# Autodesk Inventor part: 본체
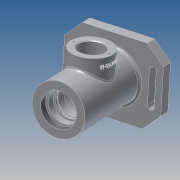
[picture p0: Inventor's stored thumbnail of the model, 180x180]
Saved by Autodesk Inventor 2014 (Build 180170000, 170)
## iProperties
Created: 2017-10
Part Number: 본체
Material: 알루미늄 6061
Document SubType Name: Modeling
Designer: kb543-05
Mass: 790.067 g
Surface Area: 665.368 cm^2
Volume: 291.538 cm^3
Density: 2.71 g/cm^3
Appearance: 알루미늄 - 평지
Author: kb543-05
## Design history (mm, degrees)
sketch "스케치2"
  geometry: L1 (0, 0)-(31, 0); L2 (31, 0)-(31, -99); L3 (31, -99)-(0, -99); L4 (0, -99)-(0, 0)
  constraints: 8 end point, 2 parallel, 1 horizontal, 1 perpendicular
  dimensions: "d1" = 99 distance of L1.end L2.end; "d2" = 62 diameter of L2 L4
revolve "회전1" sketch "스케치2" stored, may be unused: angle "d3" = 90 deg
sketch "스케치3"
  geometry: L1 (-58, 47)-(58, 47); L2 (58, 47)-(58, -47); L3 (58, -47)-(-58, -47); L4 (-58, -47)-(-58, 47); L5 (-87.549, 0)-(134.549, 0); L6 (0, 69.118)-(0, -96.765); L7 (-46, 20)-(-46, -20); L8 (-50, 20)-(-50, -20); L9 (-42, -20)-(-42, 20); L10 (46, 18)-(46, -22); L11 (42, 18)-(42, -22); L12 (50, -22)-(50, 18); C1 r 31 at (0, 0) reference; C2 r 31 at (0, 0); A1 r 4 centre (-46, 20) between (-42, 20) and (-50, 20); A2 r 4 centre (-46, -20) between (-50, -20) and (-42, -20); A3 r 4 centre (46, 18) between (50, 18) and (42, 18); A4 r 4 centre (46, -22) between (42, -22) and (50, -22); 5 further points
  constraints: 28 end point, 8 point on circle, 8 tangent, 7 parallel, 5 centre point, 5 midpoint, 3 perpendicular, 2 equal radius, 2 horizontal alignment, 2 point on line, 1 coincident, 1 horizontal, 1 vertical alignment
  dimensions: "d4" = 94 distance of L1.end L2.end; "d5" = 116 distance of L1.start L1.end; "d6" = 40 distance of L7.start L7.end; "d7" = 46 distance between parallel lines of L7 L6; "d8" = 4 radius of A1; "d9" = 92 distance between parallel lines of L7 L10
extrude "돌출1" join sketch "스케치3" distance "d10" = 13; taper "d11" = 0 deg
chamfer "모따기1" distance "d12" = 20; stored, may be unused: second distance "d13" = 2, angle "d14" = 45 deg
sketch "스케치4"
  geometry: C1 r 35 at (0, 0); 1 further point
  constraints: 1 centre point, 1 coincident
  dimensions: "d15" = 70 diameter of C1
extrude "돌출2" join sketch "스케치4" distance "d16" = 3; taper "d17" = 0 deg
sketch "스케치5"
  geometry: L1 (-31, -99)-(31, -99) reference; L2 (-31, 0)-(31, 0) reference; L3 (47, -112)-(27, -112) reference; L4 (27, -112)-(27, -99) reference; L5 (27, -99)-(47, -99) reference; L6 (47, -99)-(47, -112) reference; L7 (-35, -115)-(35, -115) reference; L8 (35, -112)-(-35, -112) reference; L9 (18, -99)-(-22, -99) reference; L10 (18, -99)-(18, -112) reference; L11 (-22, -112)-(18, -112) reference; L12 (-22, -99)-(-22, -112) reference; L13 (-35, -112)-(-47, -112) reference; L14 (-47, -112)-(-47, -99) reference; L15 (-47, -99)-(-31, -99) reference; L16 (-31, -99)-(-31, 0) reference; L17 (-31, 0)-(31, 0) reference; L18 (31, 0)-(31, -99) reference; L19 (0, 0)-(21, 0); L20 (21, 0)-(21, -9); L21 (21, -9)-(0, -9); L22 (0, -9)-(0, 0); L23 (0, -9)-(24, -9); L24 (24, -9)-(24, -12); L25 (24, -12)-(0, -12); L26 (0, -12)-(0, -9); L27 (0, -12)-(20, -12); L28 (20, -12)-(20, -21); L29 (20, -21)-(0, -21); L30 (0, -21)-(0, -12); L31 (0, -21)-(17.5, -21); L32 (17.5, -21)-(17.5, -37); L33 (17.5, -37)-(0, -37); L34 (0, -37)-(0, -21); L35 (0, -24.25)-(18.5, -24.25); L36 (18.5, -24.25)-(18.5, -26); L37 (18.5, -26)-(0, -26); L38 (0, -26)-(0, -24.25); L39 (0, -37)-(26, -37); L40 (26, -37)-(26, -75); L41 (26, -75)-(0, -75); L42 (0, -75)-(0, -37); L43 (0, -75)-(17.5, -75); L44 (17.5, -75)-(17.5, -86); L45 (17.5, -86)-(0, -86); L46 (0, -86)-(0, -75); L47 (0, -86)-(16.5, -86); L48 (16.5, -86)-(16.5, -91); L49 (16.5, -91)-(0, -91); L50 (0, -91)-(0, -86); L51 (0, -91)-(10, -91); L52 (10, -91)-(10, -93.7); L53 (10, -93.7)-(0, -93.7); L54 (0, -93.7)-(0, -91); L55 (0, -93.7)-(12.5, -93.7); L56 (12.5, -93.7)-(12.5, -101); L57 (12.5, -101)-(0, -101); L58 (0, -101)-(0, -93.7); L59 (0, -115)-(22, -115); L60 (22, -115)-(16, -101); L61 (16, -101)-(0, -101); L62 (0, -101)-(0, -115); L63 (31, -99)-(47, -99) reference; L64 (47, -99)-(47, -112) reference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
  constraints: 92 end point, 21 parallel, 13 perpendicular, 10 horizontal, 4 point on line, 2 collinear
  dimensions: "d19" = 12 distance between parallel lines of L25 L2; "d20" = 3 distance of L23.end L24.end; "d21" = 21 distance between parallel lines of L19 L29; "d22" = 26 distance between parallel lines of L37 L2; "d23" = 38 distance between parallel lines of L41 L39; "d24" = 60 distance between parallel lines of L45 L37; "d25" = 11 distance between parallel lines of L33 L37; "d26" = 1.75 distance between parallel lines of L37 L35; "d27" = 5 distance between parallel lines of L49 L45; "d29" = 7.3 distance of L55.end L56.end; "d30" = 44 diameter of L59.end L62; "d31" = 32 diameter of L60.end L62; "d32" = 25 diameter of L56 L58; "d34" = 14 distance of L61.end L59.start; "d35" = 2.7 distance between parallel lines of L53 L49; "d36" = 42 diameter of L20 L22; "d37" = 48 diameter of L24 L26; "d38" = 40 diameter of L28 L30; "d39" = 35 diameter of L32 L34; "d40" = 37 diameter of L36 L38; "d41" = 52 diameter of L40 L42; "d42" = 35 diameter of L44 L46; "d43" = 33 diameter of L48 L50; "d44" = 20 diameter of L52 L54; "d45" = 11 distance between parallel lines of L41 L45 (derived); "d46" = 30 deg angle of L56 L69; "d47" = 0.7 distance between parallel lines of L68 L61
revolve "회전2" sketch "스케치5" stored, may be unused: angle "d48" = 90 deg
feature "스레드1" dims "d49" = 10, "d50" = 0
sketch "스케치6"
  geometry: L1 (-58, -99)-(-50, -99) reference; L2 (-50, -99)-(-50, -112) reference; L3 (-50, -112)-(-58, -112) reference; L4 (-58, -112)-(-58, -99) reference; L5 (-42, -99)-(-31, -99) reference; L6 (-31, -99)-(-31, 0) reference; L7 (-31, 0)-(-21, 0) reference; L8 (-21, 0)-(-21, -9) reference; L9 (-21, -9)-(-24, -9) reference; L10 (-24, -9)-(-24, -12) reference; L11 (-24, -12)-(-20, -12) reference; L12 (-20, -12)-(-20, -21) reference; L13 (-20, -21)-(-17.5, -21) reference; L14 (-17.5, -21)-(-17.5, -24.25) reference; L15 (-17.5, -24.25)-(-18.5, -24.25) reference; L16 (-18.5, -24.25)-(-18.5, -26) reference; L17 (-18.5, -26)-(-17.5, -26) reference; L18 (-17.5, -26)-(-17.5, -37) reference; L19 (-17.5, -37)-(-26, -37) reference; L20 (-26, -37)-(-26, -75) reference; L21 (-26, -75)-(-17.5, -75) reference; L22 (-17.5, -75)-(-17.5, -86) reference; L23 (-17.5, -86)-(-16.5, -86) reference; L24 (-16.5, -86)-(-16.5, -91) reference; L25 (-16.5, -91)-(-10, -91) reference; L26 (-10, -91)-(-10, -93.7) reference; L27 (-10, -93.7)-(-12.5, -93.7) reference; L28 (-12.5, -93.7)-(-12.5, -101) reference; L29 (-12.5, -101)-(-16, -101) reference; L30 (-16, -101)-(-22, -115) reference; L31 (-22, -115)-(-35, -115) reference; L32 (-35, -115)-(-35, -112) reference; L33 (-35, -112)-(-42, -112) reference; L34 (-42, -112)-(-42, -99) reference; L35 (31, -99)-(42, -99) reference; L36 (42, -99)-(42, -112) reference; L37 (42, -112)-(35, -112) reference; L38 (35, -112)-(35, -115) reference; L39 (35, -115)-(22, -115) reference; L40 (22, -115)-(16, -101) reference; L41 (16, -101)-(12.5, -101) reference; L42 (12.5, -101)-(12.5, -93.7) reference; L43 (12.5, -93.7)-(10, -93.7) reference; L44 (10, -93.7)-(10, -91) reference; L45 (10, -91)-(16.5, -91) reference; L46 (16.5, -91)-(16.5, -86) reference; L47 (16.5, -86)-(17.5, -86) reference; L48 (17.5, -86)-(17.5, -75) reference; L49 (17.5, -75)-(26, -75) reference; L50 (26, -75)-(26, -37) reference; L51 (26, -37)-(17.5, -37) reference; L52 (17.5, -37)-(17.5, -26) reference; L53 (17.5, -26)-(18.5, -26) reference; L54 (18.5, -26)-(18.5, -24.25) reference; L55 (18.5, -24.25)-(17.5, -24.25) reference; L56 (17.5, -24.25)-(17.5, -21) reference; L57 (17.5, -21)-(20, -21) reference; L58 (20, -21)-(20, -12) reference; L59 (20, -12)-(24, -12) reference; L60 (24, -12)-(24, -9) reference; L61 (24, -9)-(21, -9) reference; L62 (21, -9)-(21, 0) reference; L63 (21, 0)-(31, 0) reference; L64 (31, 0)-(31, -99) reference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; C1 r 25 at (0, -56)
  constraints: 4 end point, 3 midpoint, 1 centre point, 1 perpendicular, 1 point on line
  dimensions: "d52" = 50 diameter of C1
  node "절단 모서리 투영2"
node "작업 평면1"
sketch "스케치7"
  geometry: L1 (0, 0)-(0, -139); L2 (-69, -56)-(82, -56); L3 (-31, 0)-(31, 0) reference; C1 r 25 at (0, -56)
  constraints: 4 end point, 2 point on line, 1 centre point, 1 perpendicular, 1 vertical
  dimensions: "d54" = 56 distance between parallel lines of L2 L3; "d55" = 50 diameter of C1
extrude "돌출3" join sketch "스케치7" stored distance "d56" = 3; taper "d57" = 0 deg
sketch "스케치8"
  geometry: C1 r 25 at (0, 0) reference; C2 r 16 at (0, 0); 1 further point
  constraints: 1 centre point, 1 coincident
  dimensions: "d58" = 32 diameter of C2
extrude "돌출4" cut sketch "스케치8" stored distance "d59" = 3; taper "d60" = 0 deg
sketch "스케치9"
  geometry: C1 r 25 at (0, 0) reference; A1 r 20.5 centre (0, 0) between (20.5, 0) and (-20.5, 0); 1 further point
  constraints: 2 point on circle, 1 centre point, 1 coincident
  dimensions: "d61" = 41 diameter of A1
hole "구멍1" sketch "스케치9" at (20.5, 0), (-20.5, 0) diameter "d62" = 2.459; stored, may be unused: countersink angle "d66" = 82 deg, drill point angle "d68" = 118 deg; dims "d63" = 6, "d64" = 3.023, "d65" = 2, "d67" = 8
chamfer "모따기2" distance "d69" = 1; stored, may be unused: second distance "d70" = 2, angle "d71" = 45 deg
fillet "모깎기1" dims "d72" = 0.3
fillet "모깎기2" dims "d73" = 3
fillet "모깎기3" dims "d74" = 3
node "작업 평면2"
sketch "스케치10"
  geometry: L1 (0, 25)-(0, -25) reference; L2 (-78, 56)-(-16, 56) reference; 2 further points
  constraints: 1 other
  dimensions: "d75" = 10 distance from line of point (-10, 0) L1; "d76" = 56 distance from line of L2 point (-10, 0)
feature "엠보싱1" sketch "스케치10" dims "d1" = 99, "d77" = 0.5, "d78" = 0
fillet "모깎기4" dims "d79" = 3
node "솔리드1"
node "투영된 루프1"
node "투영된 루프2"
node "투영된 루프3"
node "투영된 루프4"
node "절단 모서리 투영1"
other parameters: "d53" = 47
